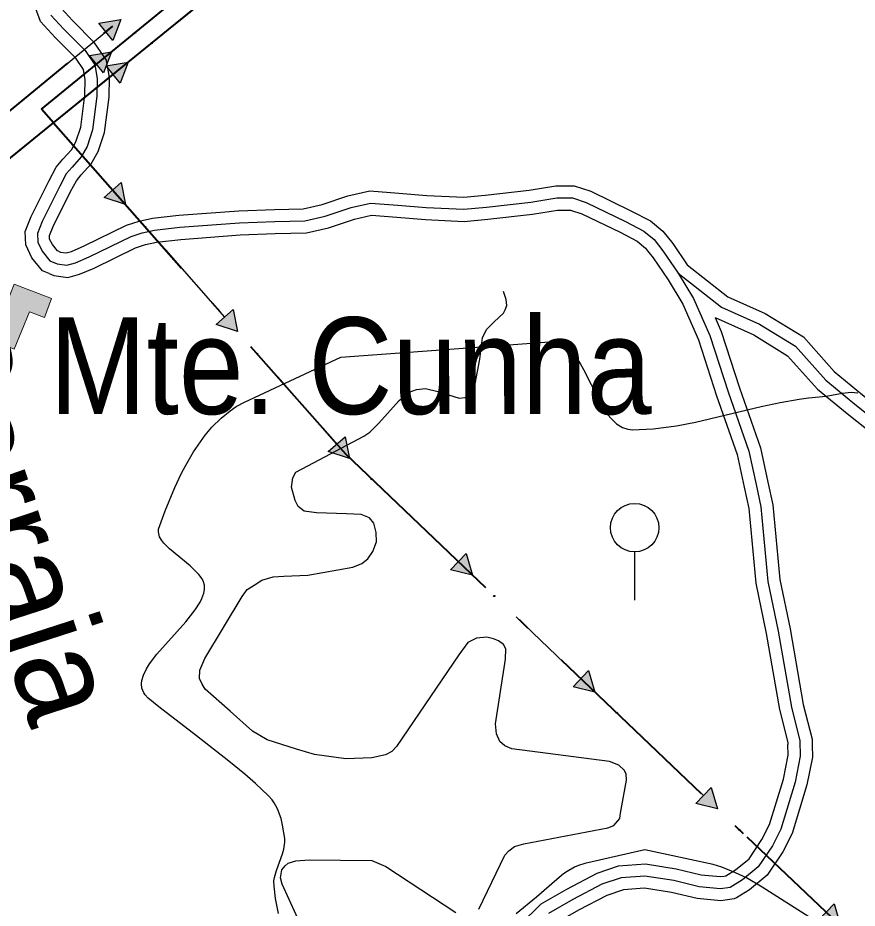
# Model space of a CAD drawing. Extents: x -64005 to -55000, y -89025 to -80000.
# Drawn here: x -60249 to -59555, y -82170 to -81434 of the extents above; entities that cross this region are included whole.
import ezdxf
from ezdxf.enums import TextEntityAlignment as Align

# ---------------------------------------------------------------- set-up
doc = ezdxf.new("R2010")
doc.units = 0
doc.header["$LTSCALE"] = 32
doc.linetypes.add('DOT_DASHED', pattern=[7.7, 5, -1.2, 0.3, -1.2])
doc.linetypes.add('LONG_DASHED', pattern=[7.5, 6, -1.5])
for name, color, linetype, lineweight in [('18', 7, 'Continuous', 25), ('24', 7, 'Continuous', 25), ('31', 7, 'Continuous', 25), ('32', 7, 'Continuous', 25), ('39', 7, 'LONG_DASHED', 25), ('7', 7, 'Continuous', 13), ('8', 7, 'Continuous', 25)]:
    doc.layers.add(name, color=color, linetype=linetype, lineweight=lineweight)
doc.layers.add('45', color=7, linetype='Continuous')

msp = doc.modelspace()

# ---------------------------------------------------------------- hatches: boundary and pattern name
at = {"layer": '18'}
for points in [[(-60182.28, -81438.78), (-60164.03, -81435.78), (-60170.55, -81453.09)], [(-60189.94, -81465.31), (-60171.68, -81462.34), (-60178.23, -81479.64)], [(-60176.26, -81473.88), (-60157.99, -81470.97), (-60164.6, -81488.25)], [(-60163.86, -81570.44), (-60160.2, -81588.57), (-60177.74, -81582.67)], [(-60071.29, -81675.47), (-60067.64, -81693.6), (-60085.17, -81687.7)], [(-59978.73, -81780.5), (-59975.08, -81798.64), (-59992.61, -81792.73)], [(-59878.66, -81877.21), (-59873.45, -81894.96), (-59891.43, -81890.6)], [(-59777.36, -81973.84), (-59772.15, -81991.59), (-59790.13, -81987.23)], [(-59676.05, -82070.47), (-59670.85, -82088.22), (-59688.82, -82083.86)], [(-59574.5, -82166.78), (-59569.22, -82184.51), (-59587.21, -82180.23)]]:
    msp.add_hatch(color=256, dxfattribs=at).paths.add_polyline_path(points)
at = {"layer": '7'}
msp.add_hatch(color=256, dxfattribs=at).paths.add_polyline_path([(-60252.26, -81654.46), (-60270.65, -81700.79), (-60252.08, -81708.22), (-60239.43, -81677.28), (-60227.11, -81682.02), (-60221.42, -81666.28)])

# ---------------------------------------------------------------- linework, layer by layer
at = {"layer": '18'}
for p, q in [((-60119.17, -81439.47), (-60061.72, -81392.85)), ((-60233.62, -81492.85), (-60176.41, -81445.94)), ((-60219.71, -81521.05), (-60170.8, -81576.55)), ((-60127.15, -81626.08), (-60078.23, -81681.59)), ((-60034.58, -81731.12), (-59985.67, -81786.62)), ((-59938.58, -81832.84), (-59885.05, -81883.9)), ((-59837.27, -81929.47), (-59783.74, -81980.54)), ((-59735.97, -82026.1), (-59682.44, -82077.17)), ((-59634.62, -82122.68), (-59580.86, -82173.5))]:
    msp.add_line(p, q, dxfattribs=at)
at = {"layer": '18', "linetype": 'DOT_DASHED', "lineweight": 40}
for points in [[(-62477.87, -83403.87), (-62367.98, -83378.64), (-62216.73, -83247.74), (-62089.34, -83137.49), (-61996.3, -83056.97), (-61098.84, -82280.26), (-60868.7, -82080.1), (-60312.19, -81596.09), (-60219.71, -81521.05), (-59047.52, -80569.92), (-58561.43, -80162.65), (-58367.89, -80000.48)], [(-60219.71, -81521.05), (-60229.69, -81509.73), (-59728.26, -81100.09), (-59529.1, -80836.33), (-59528.98, -80754.22), (-59525.88, -80631.58), (-59669.19, -80209.92), (-59798.12, -80113.85), (-59929.04, -80074.12)], [(-62504.64, -83341.78), (-62247.39, -83226.15), (-62239.3, -83222.48), (-62226.91, -83216.87), (-62023.78, -83041.07), (-61118.5, -82257.6), (-60888.39, -82057.46), (-60331.49, -81573.12), (-59784.07, -81124.16), (-59559.17, -80826.16), (-59559.05, -80755.05), (-59556.19, -80635.98), (-59694.59, -80228.4), (-59810.95, -80144.91), (-59929.04, -80078.55)], [(-60219.71, -81521.05), (-59978.44, -81794.82), (-59646.58, -82111.37), (-59468.07, -82280.13), (-59415, -82487.84), (-59283.25, -82645.5), (-59128.86, -82841.58), (-58714.75, -83353.72), (-58581.73, -83517.45), (-58506.34, -83610.82), (-58347.94, -83807.01), (-58247.59, -83933.66), (-58191.9, -84001.28), (-58164.58, -84034.46), (-58137.14, -84068.11), (-57960.33, -84286.53), (-57797.76, -84487.35), (-57624.25, -84702.51), (-57366.28, -84880.22), (-57249.59, -84960.27), (-57114.47, -85053.89), (-56518.68, -85641.19), (-56404.54, -85755.57)]]:
    msp.add_lwpolyline(points, dxfattribs=at)
at = {"layer": '18'}
for points in [[(-60182.28, -81438.78), (-60164.03, -81435.78), (-60170.55, -81453.09)], [(-60189.94, -81465.31), (-60171.68, -81462.34), (-60178.23, -81479.64)], [(-60176.26, -81473.88), (-60157.99, -81470.97), (-60164.6, -81488.25)], [(-60163.86, -81570.44), (-60160.2, -81588.57), (-60177.74, -81582.67)], [(-60071.29, -81675.47), (-60067.64, -81693.6), (-60085.17, -81687.7)], [(-59978.73, -81780.5), (-59975.08, -81798.64), (-59992.61, -81792.73)], [(-59878.66, -81877.21), (-59873.45, -81894.96), (-59891.43, -81890.6)], [(-59777.36, -81973.84), (-59772.15, -81991.59), (-59790.13, -81987.23)], [(-59676.05, -82070.47), (-59670.85, -82088.22), (-59688.82, -82083.86)], [(-59574.5, -82166.78), (-59569.22, -82184.51), (-59587.21, -82180.23)]]:
    msp.add_lwpolyline(points, close=True, dxfattribs=at)
for points in [[(-60219.71, -81521.05), (-60229.69, -81509.73), (-60184.08, -81472.47)], [(-60227.88, -81527.68), (-60219.71, -81521.05), (-60170.43, -81481.07)]]:
    msp.add_lwpolyline(points, dxfattribs=at)
for centre in [(-60152.32, -81446.52), (-60138.58, -81455.22), (-60247.29, -81543.43), (-60143.68, -81607.32), (-60051.11, -81712.36), (-59956.67, -81815.58), (-59855.36, -81912.22), (-59754.06, -82008.85), (-59652.76, -82105.48)]:
    msp.add_circle(centre, 0.5, dxfattribs=at)
at = {"layer": '24'}
for points in [[(-60073.75, -81759.14), (-60068.56, -81755.68), (-60061.73, -81752), (-59982.16, -81714.68), (-59809.73, -81702.22), (-59806.16, -81702.26), (-59802.47, -81703), (-59797.73, -81705.14), (-59794.02, -81707.87), (-59790.59, -81711.32), (-59788.44, -81713.97), (-59784.4, -81719.94), (-59781.55, -81724.89), (-59769, -81749.9), (-59765.24, -81756.6), (-59761.21, -81762.63), (-59759.06, -81765.3), (-59754.44, -81769.83), (-59749.3, -81773.03), (-59745.05, -81774.4), (-59741.2, -81774.78), (-59735.45, -81774.7), (-59723.92, -81774), (-59704.63, -81771.48), (-59689.15, -81768.54), (-59634.66, -81755.62), (-59619.04, -81752.24), (-59603.41, -81749.48), (-59595.59, -81748.4), (-59581.09, -81746.99), (-59567.8, -81744.55), (-59560.22, -81743.78), (-59554.7, -81744.27)], [(-60033.65, -82174.61), (-60036.09, -82162.18), (-60037.42, -82152.13), (-60037.45, -82147.77), (-60037.02, -82144.85), (-60035.41, -82139), (-60030.32, -82125.35), (-60029.21, -82121.46), (-60028.44, -82115.63), (-60028.59, -82112.73), (-60030.31, -82101.68), (-60031.63, -82096.14), (-60034.54, -82088.12), (-60037.29, -82083.13), (-60038.95, -82080.79), (-60041.85, -82077.49), (-60052.76, -82067.18), (-60061.55, -82059.54), (-60074.83, -82048.77), (-60101.53, -82027.75), (-60132.6, -82003.88), (-60141.32, -81996.65), (-60143.86, -81994), (-60145.11, -81992.15), (-60146.62, -81988.27), (-60146.95, -81984.86), (-60146.66, -81982.02), (-60145.39, -81977.62), (-60142.95, -81972.54), (-60140.35, -81968.34), (-60134.22, -81960.25), (-60110.25, -81933.49), (-60102.45, -81923.66), (-60098.46, -81917.33), (-60096.95, -81914.25), (-60095.38, -81909.76), (-60094.87, -81906.86), (-60094.9, -81903.36), (-60095.69, -81900.37), (-60096.89, -81897.99), (-60099.49, -81894.44), (-60106.77, -81887.38), (-60123.81, -81873.34), (-60128.41, -81868.66), (-60130.22, -81866.31), (-60132, -81863.18), (-60132.99, -81859.24), (-60132.81, -81856.87), (-60127.39, -81841.67), (-60119.46, -81822.43), (-60113.79, -81810.54), (-60110.69, -81804.62), (-60103.92, -81793.02), (-60100.24, -81787.43), (-60094.34, -81779.39), (-60088.7, -81772.71), (-60081.11, -81765.12), (-60073.75, -81759.14)], [(-59595.21, -82177.35), (-59633.77, -82152.79), (-59646.87, -82145.29), (-59655.83, -82140.9), (-59667.37, -82136.36), (-59674.52, -82134.25), (-59731, -82122.02), (-59780.58, -82133.4), (-59785.68, -82134.96), (-59788.92, -82136.36), (-59795.09, -82139.89), (-59798.05, -82141.94), (-59803.77, -82146.47), (-59820.41, -82161.05), (-59837.35, -82174.85)]]:
    msp.add_lwpolyline(points, dxfattribs=at)
at = {"layer": '32'}
msp.add_line((-59739.3, -81875.73), (-59739.3, -81915.73), dxfattribs=at)
msp.add_circle((-59739.3, -81855.73), 20, dxfattribs=at)
at = {"layer": '39'}
for points in [[(-60221.79, -81431.98), (-60211.08, -81443.53), (-60193.62, -81461.27), (-60185.45, -81473.1), (-60183.48, -81484.37), (-60183.76, -81499.01), (-60187.42, -81526.9), (-60191.93, -81540.71), (-60196.72, -81549.16), (-60204.32, -81557.61), (-60209.11, -81563.25), (-60214.46, -81573.39), (-60229.11, -81602.68), (-60233.05, -81612.55), (-60232.77, -81619.59), (-60229.11, -81627.2), (-60222.63, -81635.08), (-60216.71, -81637.61), (-60208.55, -81638.74), (-60201.5, -81636.76), (-60190.24, -81631.98), (-60155.59, -81615.07), (-60146.3, -81611.97), (-60136.16, -81609.71), (-60115.31, -81607.46), (-60066.01, -81603.79), (-60036.72, -81602.66), (-60011.93, -81602.1), (-59995.03, -81598.16), (-59973.63, -81591.1), (-59957.57, -81587.44), (-59935.03, -81589.13), (-59911.65, -81591.1), (-59880.38, -81592.5), (-59861.79, -81590.81), (-59825.18, -81586.58), (-59803.77, -81583.2), (-59790.82, -81583.2), (-59779.26, -81586.86), (-59746.86, -81602.64), (-59731.65, -81610.52), (-59723.2, -81617.56), (-59715.88, -81626.85), (-59703.21, -81645.44)], [(-59703.21, -81645.44), (-59690.53, -81666.29), (-59677.29, -81697), (-59662.08, -81743.47), (-59644.9, -81792.49), (-59638.99, -81820.09), (-59635.04, -81838.4), (-59629.13, -81900.09), (-59620.68, -81941.21), (-59609.69, -82004.04), (-59602.65, -82031.92), (-59602.37, -82044.6), (-59606.59, -82066), (-59618.42, -82104.88), (-59625.46, -82118.68), (-59637.29, -82136.15), (-59650.26, -82146.85), (-59660.4, -82153.05), (-59668.29, -82154.18), (-59686.03, -82152.49), (-59706.88, -82147.43), (-59730.82, -82143.77), (-59750.53, -82145.17), (-59766.31, -82150.53), (-59790.53, -82163.21), (-59810.54, -82174.76)], [(-59703.21, -81645.44), (-59667.5, -81673.52), (-59635.98, -81687.58), (-59606.35, -81705.81), (-59581.29, -81733.92), (-59557.36, -81753.67), (-59526.22, -81778.36), (-59509.89, -81796.59), (-59481.02, -81840.66), (-59455.95, -81879.98), (-59435.82, -81901.63), (-59410.37, -81920.25), (-59385.31, -81941.9), (-59353.02, -81980.26), (-59334.03, -82004.96), (-59316.18, -82038.01), (-59309.34, -82063.84), (-59307.06, -82101.25), (-59297.94, -82127.47), (-59287.68, -82152.54), (-59281.6, -82165.07), (-59280.08, -82185.59)]]:
    msp.add_lwpolyline(points, dxfattribs=at)
at = {"layer": '7'}
msp.add_lwpolyline([(-60252.26, -81654.46), (-60270.65, -81700.79), (-60252.08, -81708.22), (-60239.43, -81677.28), (-60227.11, -81682.02), (-60221.42, -81666.28)], close=True, dxfattribs=at)
at = {"layer": '7', "lineweight": 25}
for points in [[(-60098.72, -81973.52), (-60094.5, -81963.96), (-60063.62, -81912.63), (-60059.57, -81906.75), (-60053.69, -81903.25), (-60047.44, -81899.02), (-60038.06, -81896.44), (-60029.42, -81895.71), (-60009.38, -81894.97), (-59972.24, -81888.35), (-59964.71, -81885.41), (-59959.74, -81881.36), (-59955.7, -81875.47), (-59952.76, -81867.38), (-59952.94, -81859.84), (-59954.97, -81851.93), (-59958.46, -81847.51), (-59965.26, -81844.75), (-59977.4, -81844.2), (-60002.4, -81843.47), (-60012.51, -81842.19), (-60017.48, -81838.32), (-60020.05, -81833.17), (-60023, -81822.32), (-60021.89, -81814.42), (-60019.32, -81809.82), (-60009.39, -81804.48), (-59963.25, -81780.01), (-59958.1, -81776.88), (-59950.75, -81769.34), (-59933.84, -81750.58), (-59925.75, -81743.77), (-59919.68, -81741.56), (-59912.33, -81740.64), (-59902.03, -81743.03), (-59884.38, -81748.73), (-59879.42, -81748), (-59875.56, -81744.69), (-59871.15, -81736.96), (-59867.29, -81716.55), (-59865.09, -81698.89), (-59861.78, -81691.9), (-59855.53, -81685.64), (-59847.81, -81678.28), (-59846.34, -81675.53), (-59845.05, -81672.21), (-59845.6, -81667.06), (-59847.81, -81660.63)], [(-59867.99, -82171.02), (-59846.48, -82126.5), (-59843.35, -82122.82), (-59838.76, -82119.14), (-59831.04, -82117.12), (-59761.36, -82103.87), (-59756.58, -82101.84), (-59751.62, -82096.14), (-59750.88, -82091.73), (-59746.11, -82064.5), (-59746.29, -82059.17), (-59747.95, -82056.23), (-59752.36, -82052), (-59760.08, -82049.06), (-59840.79, -82038.58), (-59846.49, -82036.01), (-59850.72, -82032.52), (-59853.48, -82026.26), (-59854.4, -82017.99), (-59846.13, -81964.46), (-59845.77, -81955.82), (-59847.6, -81952.32), (-59851.83, -81949.2), (-59855.88, -81947.54), (-59861.39, -81946.26), (-59870.03, -81947.18), (-59877.2, -81950.67), (-59884.56, -81960.79), (-59936.21, -82036.58), (-59940.07, -82040.63), (-59945.22, -82043.39), (-59956.61, -82045.96), (-59977.93, -82046.71), (-60003.86, -82043.22), (-60018.93, -82038.8), (-60043.02, -82031.08), (-60055.15, -82023.91), (-60073.54, -82007.36), (-60094.31, -81989.16), (-60096.88, -81985.11), (-60099.09, -81980.51), (-60098.72, -81973.52)], [(-60007.53, -82201.02), (-60030.7, -82150.44), (-60032.17, -82145.29), (-60030.88, -82138.66), (-60028.12, -82135.35), (-60025.73, -82132.96), (-60019.3, -82131.12), (-60008.27, -82130.2), (-59956.42, -82130.93), (-59948.89, -82134.05), (-59945.03, -82135.71), (-59887.11, -82173.96)]]:
    msp.add_lwpolyline(points, dxfattribs=at)
at = {"layer": '8', "linetype": 'LONG_DASHED'}
for points in [[(-60223.31, -81645.67), (-60228.81, -81643.31), (-60237.6, -81632.62), (-60242.68, -81622.06), (-60243.13, -81610.82), (-60238.24, -81598.58), (-60223.36, -81568.82), (-60217.44, -81557.61), (-60211.85, -81551.03), (-60204.88, -81543.28), (-60201.12, -81536.65), (-60197.21, -81524.69), (-60193.75, -81498.26), (-60193.5, -81485.14), (-60194.88, -81477.19), (-60194.92, -81476.98), (-60201.36, -81467.67), (-60218.31, -81450.44), (-60230.53, -81437.26), (-60234.49, -81426.08)], [(-60215.53, -81627.23), (-60214, -81627.89), (-60209.25, -81628.55), (-60204.82, -81627.31), (-60194.39, -81622.88), (-60159.38, -81605.79), (-60148.97, -81602.32), (-60137.79, -81599.83), (-60116.22, -81597.5), (-60066.57, -81593.8), (-60037.03, -81592.66), (-60013.19, -81592.13), (-59997.74, -81588.52), (-59976.31, -81581.45), (-59958.32, -81577.36), (-59934.24, -81579.16), (-59911, -81581.11), (-59880.61, -81582.48), (-59862.82, -81580.86), (-59826.53, -81576.67), (-59804.55, -81573.2), (-59789.28, -81573.2), (-59775.55, -81577.55), (-59742.38, -81593.7), (-59726.09, -81602.13), (-59715.99, -81610.55)], [(-59715.99, -81610.55), (-59707.81, -81620.93), (-59695.81, -81638.54)], [(-59728.57, -81626.91), (-59723.95, -81632.78), (-59711.62, -81650.87), (-59699.44, -81670.9), (-59686.65, -81700.55), (-59671.55, -81746.69), (-59654.55, -81795.2), (-59648.77, -81822.19), (-59644.94, -81839.94), (-59639.03, -81901.58), (-59630.5, -81943.08), (-59619.48, -82006.13), (-59612.62, -82033.27), (-59612.58, -82035.05)], [(-59672.83, -81682.09), (-59667.93, -81693.46), (-59652.61, -81740.25), (-59635.25, -81789.78), (-59629.21, -81817.99), (-59625.14, -81836.86), (-59619.23, -81898.6), (-59610.86, -81939.34), (-59599.9, -82001.94), (-59592.68, -82030.57), (-59592.57, -82035.48)], [(-59672.83, -81682.09), (-59640.66, -81696.44), (-59612.84, -81713.56), (-59588.25, -81741.15), (-59563.65, -81761.44), (-59533.1, -81785.67), (-59517.84, -81802.7), (-59489.42, -81846.09), (-59463.89, -81886.12), (-59442.49, -81909.14), (-59416.6, -81928.08), (-59392.45, -81948.95), (-59360.81, -81986.53), (-59342.45, -82010.42), (-59325.54, -82041.72), (-59319.26, -82065.44), (-59316.96, -82103.23), (-59307.3, -82131.01), (-59296.82, -82156.62), (-59291.43, -82167.72), (-59290.04, -82186.54)], [(-59834.84, -82184.63), (-59816.64, -82166.74), (-59795.35, -82154.45), (-59770.26, -82141.31), (-59752.53, -82135.29), (-59730.41, -82133.72), (-59704.94, -82137.61), (-59684.37, -82142.6), (-59668.53, -82144.11), (-59665.38, -82143.66), (-59663.86, -82143.44), (-59656.08, -82138.69), (-59644.76, -82129.35), (-59634.09, -82113.59), (-59627.73, -82101.12), (-59616.3, -82063.57), (-59612.39, -82043.73), (-59612.58, -82035.05)]]:
    msp.add_lwpolyline(points, dxfattribs=at)
at = {"layer": '8'}
for points in [[(-60215.53, -81627.23), (-60216.45, -81626.84), (-60220.62, -81621.77), (-60222.86, -81617.11), (-60222.97, -81614.27), (-60219.98, -81606.78), (-60205.56, -81577.96), (-60200.78, -81568.89), (-60196.79, -81564.19), (-60188.56, -81555.04), (-60182.74, -81544.76), (-60177.63, -81529.12), (-60173.77, -81499.76), (-60173.46, -81483.6), (-60175.92, -81469.54), (-60175.98, -81469.22), (-60185.88, -81454.87), (-60203.85, -81436.62), (-60213.05, -81426.7)], [(-60223.31, -81645.67), (-60219.42, -81647.34), (-60207.85, -81648.93), (-60198.18, -81646.21), (-60186.09, -81641.08), (-60151.8, -81624.35), (-60143.63, -81621.63), (-60134.53, -81619.59), (-60114.4, -81617.42), (-60065.45, -81613.79), (-60036.41, -81612.66), (-60010.67, -81612.07), (-59992.32, -81607.8), (-59970.95, -81600.75), (-59956.82, -81597.52), (-59935.82, -81599.1), (-59912.3, -81601.08), (-59880.15, -81602.52), (-59860.76, -81600.76), (-59823.83, -81596.5), (-59802.99, -81593.2), (-59792.37, -81593.2), (-59782.99, -81596.17), (-59751.35, -81611.58), (-59737.22, -81618.9), (-59730.41, -81624.58), (-59728.57, -81626.91)], [(-59695.81, -81638.54), (-59662.29, -81664.89), (-59631.3, -81678.72), (-59599.86, -81698.06), (-59574.33, -81726.69), (-59551.07, -81745.9), (-59519.34, -81771.05), (-59501.94, -81790.48), (-59472.62, -81835.23), (-59448.01, -81873.84), (-59429.15, -81894.12), (-59404.14, -81912.42), (-59378.17, -81934.85), (-59345.23, -81973.99), (-59325.61, -81999.5), (-59306.82, -82034.3), (-59299.42, -82062.24), (-59297.16, -82099.27), (-59288.58, -82123.93), (-59278.54, -82148.46), (-59271.77, -82162.42), (-59270.12, -82184.64)], [(-59592.57, -82035.48), (-59592.35, -82045.47), (-59596.88, -82068.43), (-59609.11, -82108.64), (-59616.83, -82123.78), (-59629.82, -82142.95), (-59644.43, -82155.01), (-59655.23, -82161.61)], [(-59655.23, -82161.61), (-59656.94, -82162.66), (-59668.05, -82164.25), (-59687.69, -82162.38), (-59708.82, -82157.25), (-59731.23, -82153.82), (-59748.53, -82155.05), (-59762.36, -82159.75), (-59785.71, -82171.97), (-59804.43, -82182.78), (-59820.04, -82198.13), (-59836.96, -82218.87), (-59863.46, -82255.99), (-59902.93, -82313.67), (-59919.52, -82341.7), (-59928.8, -82352.78), (-59935.99, -82361.23), (-59950.46, -82389.01)]]:
    msp.add_lwpolyline(points, dxfattribs=at)

# ---------------------------------------------------------------- texts
at = {"layer": '31'}
msp.add_text('Sorraia', height=80, rotation=287.943, dxfattribs=at).set_placement((-60344.42, -81695.06))
at = {"layer": '45', "width": 0.9}
msp.add_text('Mte. Cunha', height=80, rotation=0.007, dxfattribs=at).set_placement((-59974.17, -81761.81), align=Align.CENTER)

doc.saveas('drawing.dxf')
